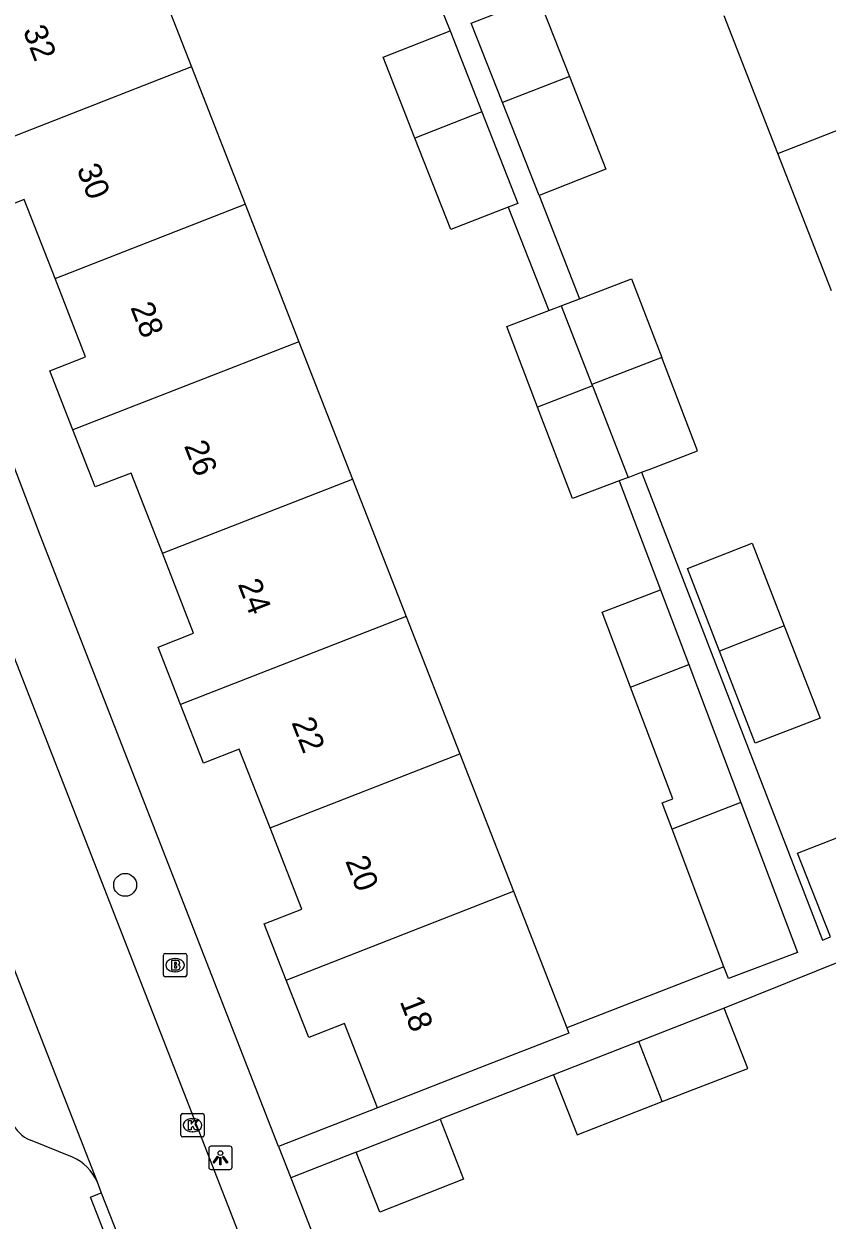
# Model space of a CAD drawing. Extents: x 159689 to 160786, y 387323 to 388339.
# Drawn here: x 160091.8 to 160126.1, y 387520.9 to 387572 of the extents above; entities that cross this region are included whole.
import ezdxf

# ---------------------------------------------------------------- set-up
doc = ezdxf.new("R2010")
doc.units = 0
for name, color, linetype in [('IMGEO_Boom', 7, 'Continuous'), ('IMGEO_Brandkraan', 7, 'Continuous'), ('IMGEO_Kolk', 7, 'Continuous'), ('IMGEO_Lichtpunt', 7, 'Continuous'), ('IMGEO_Pand', 7, 'Continuous'), ('IMGEO_Pand_nummerreeks', 7, 'Continuous'), ('IMGEO_Rijbaan_lokaal_open', 7, 'Continuous'), ('IMGEO_Voetpad_open', 7, 'Continuous')]:
    doc.layers.add(name, color=color, linetype=linetype)

msp = doc.modelspace()

# ---------------------------------------------------------------- linework, layer by layer
at = {"layer": 'IMGEO_Boom'}
msp.add_circle((160096.152, 387535.245), 0.489, dxfattribs=at)
at = {"layer": 'IMGEO_Brandkraan'}
for p, q in [((160097.786, 387531.391), (160097.786, 387532.243)), ((160097.861, 387532.317), (160098.713, 387532.317)), ((160098.787, 387532.243), (160098.787, 387531.391)), ((160098.274, 387532.097), (160098.299, 387532.097)), ((160098.713, 387531.317), (160097.861, 387531.317)), ((160098.297, 387531.537), (160098.272, 387531.537))]:
    msp.add_line(p, q, dxfattribs=at)
for points in [[(160097.786, 387531.391), (160097.786, 387532.243)], [(160097.861, 387532.317), (160098.713, 387532.317)], [(160098.787, 387532.243), (160098.787, 387531.391)], [(160098.134, 387532.017), (160098.134, 387531.617), (160098.347, 387531.617)], [(160098.365, 387532.017), (160098.134, 387532.017)], [(160098.313, 387531.936), (160098.259, 387531.936), (160098.259, 387531.86)], [(160098.259, 387531.86), (160098.312, 387531.86)], [(160098.321, 387531.784), (160098.259, 387531.784), (160098.259, 387531.703)], [(160098.259, 387531.703), (160098.321, 387531.703)], [(160098.713, 387531.317), (160097.861, 387531.317)]]:
    msp.add_lwpolyline(points, dxfattribs=at)
for centre, radius, start, end in [((160097.863, 387532.241), 0.0765, 91.552, 178.448), ((160097.863, 387532.241), 0.0765, 91.552, 178.448), ((160098.711, 387532.241), 0.0765, 1.552, 88.448), ((160098.711, 387532.241), 0.0765, 1.552, 88.448), ((160098.314, 387531.898), 0.0379, 267.8285, 90.9355), ((160098.322, 387531.743), 0.0404, 269.8759, 90.5077), ((160098.369, 387531.872), 0.145, 59.4692, 91.5367), ((160098.394, 387531.919), 0.0922, 285.5137, 58.1501), ((160098.399, 387531.727), 0.105, 301.3115, 78.989), ((160097.863, 387531.393), 0.0765, 181.552, 268.448), ((160097.863, 387531.393), 0.0765, 181.552, 268.448), ((160098.353, 387531.868), 0.251, 268.6676, 293.5347), ((160098.711, 387531.393), 0.0765, 271.552, 358.448), ((160098.711, 387531.393), 0.0765, 271.552, 358.448)]:
    msp.add_arc(centre, radius, start, end, dxfattribs=at)
for centre, major_axis, ratio, start_param, end_param in [((160098.273, 387531.817), (-0.387, 0.002), 0.722429, 4.712389, 7.853982), ((160098.298, 387531.817), (-0.39, 0.002), 0.717154, 1.570796, 4.712389)]:
    msp.add_ellipse(centre, major_axis=major_axis, ratio=ratio, start_param=start_param, end_param=end_param, dxfattribs=at)
at = {"layer": 'IMGEO_Kolk'}
for p, q in [((160098.531, 387524.551), (160098.531, 387525.403)), ((160098.606, 387525.477), (160099.458, 387525.477)), ((160099.019, 387525.257), (160099.044, 387525.257)), ((160099.532, 387525.403), (160099.532, 387524.551)), ((160099.042, 387524.697), (160099.017, 387524.697)), ((160099.458, 387524.477), (160098.606, 387524.477))]:
    msp.add_line(p, q, dxfattribs=at)
for points in [[(160098.531, 387524.551), (160098.531, 387525.403)], [(160098.606, 387525.477), (160099.458, 387525.477)], [(160098.852, 387525.177), (160098.975, 387525.177), (160098.975, 387525.026), (160099.105, 387525.177), (160099.269, 387525.177), (160099.123, 387525.026), (160099.276, 387524.777), (160099.124, 387524.777), (160099.039, 387524.941), (160098.975, 387524.874), (160098.975, 387524.777), (160098.852, 387524.777), (160098.852, 387525.177)], [(160099.532, 387525.403), (160099.532, 387524.551)], [(160099.458, 387524.477), (160098.606, 387524.477)]]:
    msp.add_lwpolyline(points, dxfattribs=at)
for centre, start, end in [((160098.608, 387525.401), 91.552, 178.448), ((160098.608, 387525.401), 91.552, 178.448), ((160099.456, 387525.401), 1.552, 88.448), ((160099.456, 387525.401), 1.552, 88.448), ((160098.608, 387524.553), 181.552, 268.448), ((160098.608, 387524.553), 181.552, 268.448), ((160099.456, 387524.553), 271.552, 358.448), ((160099.456, 387524.553), 271.552, 358.448)]:
    msp.add_arc(centre, 0.0765, start, end, dxfattribs=at)
for centre, major_axis, ratio, start_param, end_param in [((160099.018, 387524.977), (-0.387, 0.002), 0.722429, 4.712389, 7.853982), ((160099.043, 387524.977), (-0.39, 0.002), 0.717154, 1.570796, 4.712389)]:
    msp.add_ellipse(centre, major_axis=major_axis, ratio=ratio, start_param=start_param, end_param=end_param, dxfattribs=at)
at = {"layer": 'IMGEO_Lichtpunt'}
for p, q in [((160100.624, 387524.085), (160099.816, 387524.085)), ((160100.624, 387524.085), (160099.816, 387524.085)), ((160099.722, 387523.99), (160099.722, 387523.183)), ((160099.722, 387523.99), (160099.722, 387523.183)), ((160100.718, 387523.183), (160100.718, 387523.99)), ((160100.718, 387523.183), (160100.718, 387523.99)), ((160099.816, 387523.089), (160100.624, 387523.089)), ((160099.816, 387523.089), (160100.624, 387523.089))]:
    msp.add_line(p, q, dxfattribs=at)
for points in [[(160100.096, 387523.654), (160100.135, 387523.626), (160099.947, 387523.364), (160099.909, 387523.391), (160100.096, 387523.654)], [(160100.198, 387523.606), (160100.245, 387523.606), (160100.245, 387523.284), (160100.198, 387523.284), (160100.198, 387523.606)], [(160100.308, 387523.626), (160100.346, 387523.653), (160100.533, 387523.391), (160100.494, 387523.363), (160100.308, 387523.626)]]:
    msp.add_lwpolyline(points, dxfattribs=at)
msp.add_circle((160100.221, 387523.788), 0.0994, dxfattribs=at)
for centre, start, end in [((160099.816, 387523.99), 90, 180), ((160099.816, 387523.99), 90, 180), ((160100.624, 387523.99), 0, 90), ((160100.624, 387523.99), 0, 90), ((160099.816, 387523.183), 180, 270), ((160099.816, 387523.183), 180, 270), ((160100.624, 387523.183), 270, 0), ((160100.624, 387523.183), 270, 360)]:
    msp.add_arc(centre, 0.0946, start, end, dxfattribs=at)
at = {"layer": 'IMGEO_Pand'}
for points in [[(160096.697, 387576.052), (160098.989, 387570.183)], [(160110.938, 387572.052), (160113.797, 387573.175), (160115.13, 387569.781)], [(160124.032, 387566.492), (160121.745, 387572.362)], [(160108.53, 387567.146), (160107.174, 387570.597), (160110.033, 387571.719)], [(160110.033, 387571.719), (160111.39, 387568.263)], [(160112.268, 387568.665), (160110.938, 387572.052)], [(160098.989, 387570.183), (160089.379, 387566.43)], [(160098.989, 387570.183), (160101.281, 387564.315)], [(160124.032, 387566.492), (160133.59, 387570.221)], [(160115.13, 387569.781), (160112.268, 387568.665)], [(160115.13, 387569.781), (160116.689, 387565.81), (160113.831, 387564.687)], [(160113.831, 387564.687), (160112.268, 387568.665)], [(160111.39, 387568.263), (160108.53, 387567.146)], [(160111.39, 387568.263), (160112.926, 387564.355), (160112.513, 387564.193)], [(160112.513, 387564.193), (160110.067, 387563.232), (160108.53, 387567.146)], [(160126.319, 387560.621), (160124.032, 387566.492)], [(160093.159, 387561.143), (160091.842, 387564.514), (160090.354, 387563.933), (160089.379, 387566.43)], [(160093.159, 387561.143), (160101.281, 387564.315)], [(160101.281, 387564.315), (160103.574, 387558.447)], [(160093.923, 387554.679), (160092.937, 387557.201), (160094.465, 387557.798), (160093.159, 387561.143)], [(160115.554, 387560.279), (160117.787, 387561.134), (160119.074, 387557.774)], [(160114.247, 387559.779), (160114.775, 387559.981)], [(160114.775, 387559.981), (160115.554, 387560.279)], [(160114.775, 387559.981), (160116.089, 387556.612)], [(160113.771, 387555.648), (160112.453, 387559.091), (160114.247, 387559.779)], [(160103.574, 387558.447), (160093.923, 387554.679)], [(160103.574, 387558.447), (160105.866, 387552.579)], [(160119.074, 387557.774), (160116.089, 387556.612)], [(160118.212, 387552.87), (160118.531, 387552.992), (160120.601, 387553.785), (160119.074, 387557.774)], [(160116.109, 387556.561), (160113.771, 387555.648)], [(160116.089, 387556.612), (160116.109, 387556.561)], [(160116.109, 387556.561), (160117.635, 387552.649)], [(160117.255, 387552.503), (160115.267, 387551.742), (160113.771, 387555.648)], [(160097.745, 387549.407), (160096.405, 387552.837), (160094.876, 387552.24), (160093.923, 387554.679)], [(160117.635, 387552.649), (160117.255, 387552.503)], [(160117.635, 387552.649), (160118.212, 387552.87)], [(160097.745, 387549.407), (160105.866, 387552.579)], [(160105.866, 387552.579), (160108.158, 387546.711)], [(160121.541, 387545.23), (160120.17, 387548.765), (160122.939, 387549.839), (160124.308, 387546.31)], [(160098.517, 387542.946), (160097.556, 387545.405), (160099.076, 387545.999), (160097.745, 387549.407)], [(160117.739, 387543.688), (160116.527, 387546.899), (160119.027, 387547.843)], [(160119.027, 387547.843), (160120.229, 387544.661)], [(160108.158, 387546.711), (160098.517, 387542.946)], [(160108.158, 387546.711), (160110.45, 387540.842)], [(160124.308, 387546.31), (160125.837, 387542.369), (160123.068, 387541.295), (160121.541, 387545.23)], [(160124.308, 387546.31), (160121.541, 387545.23)], [(160117.739, 387543.688), (160120.229, 387544.661)], [(160120.229, 387544.661), (160122.453, 387538.766)], [(160119.512, 387537.618), (160119.086, 387538.746), (160119.54, 387538.917), (160117.739, 387543.688)], [(160102.34, 387537.675), (160101.024, 387541.045), (160099.493, 387540.448), (160098.517, 387542.946)], [(160102.34, 387537.675), (160110.45, 387540.842)], [(160110.45, 387540.842), (160112.742, 387534.974)], [(160122.453, 387538.766), (160119.512, 387537.618)], [(160122.453, 387538.766), (160124.872, 387532.358), (160121.918, 387531.243), (160121.726, 387531.751)], [(160103.032, 387531.182), (160102.094, 387533.584), (160103.694, 387534.209), (160102.34, 387537.675)], [(160121.726, 387531.751), (160119.512, 387537.618)], [(160126.275, 387533.021), (160124.879, 387536.597), (160127.654, 387537.681), (160128.416, 387535.73), (160130.197, 387536.425), (160130.785, 387534.923)], [(160103.032, 387531.182), (160112.742, 387534.974)], [(160112.742, 387534.974), (160115.024, 387529.133)], [(160106.936, 387525.72), (160105.527, 387529.326), (160103.992, 387528.726), (160103.032, 387531.182)], [(160121.746, 387529.978), (160118.097, 387528.553)], [(160119.098, 387525.986), (160122.75, 387527.408), (160121.746, 387529.978)], [(160115.024, 387529.133), (160115.11, 387528.913), (160111.594, 387527.54), (160106.936, 387525.72)], [(160118.097, 387528.553), (160114.455, 387527.131)], [(160119.098, 387525.986), (160118.097, 387528.553)], [(160114.455, 387527.131), (160115.454, 387524.566), (160119.098, 387525.986)], [(160109.602, 387525.235), (160110.609, 387522.679), (160107.035, 387521.27), (160106.027, 387523.827)], [(160106.027, 387523.827), (160109.602, 387525.235)]]:
    msp.add_lwpolyline(points, dxfattribs=at)
at = {"layer": 'IMGEO_Rijbaan_lokaal_open'}
for points in [[(160108.108, 387502.148), (160086.248, 387558.199), (160073.949, 387589.946)], [(160069.872, 387586.748), (160082.582, 387554.195), (160094.951, 387522.558)], [(160094.951, 387522.558), (160095.132, 387522.093)], [(160095.132, 387522.093), (160096.916, 387517.531), (160097.168, 387516.715)]]:
    msp.add_lwpolyline(points, dxfattribs=at)
at = {"layer": 'IMGEO_Voetpad_open'}
for points in [[(160102.702, 387524.071), (160092.528, 387550.187), (160079.92, 387583.288), (160078.337, 387587.445)], [(160108.237, 387576.163), (160110.033, 387571.719)], [(160113.831, 387564.687), (160115.554, 387560.279)], [(160112.513, 387564.193), (160114.247, 387559.779)], [(160118.212, 387552.87), (160125.946, 387532.883), (160126.275, 387533.021)], [(160117.255, 387552.503), (160119.027, 387547.843)], [(160149.389, 387541.094), (160121.746, 387529.978)], [(160121.726, 387531.751), (160115.024, 387529.133)], [(160114.455, 387527.131), (160109.602, 387525.235)], [(160106.936, 387525.72), (160102.702, 387524.071)], [(160093.909, 387523.61), (160092.105, 387524.337)], [(160102.702, 387524.071), (160103.223, 387522.735)], [(160106.027, 387523.827), (160103.223, 387522.735)], [(160103.223, 387522.735), (160111.039, 387502.671)], [(160097.168, 387516.715), (160096.761, 387516.556), (160094.667, 387521.911), (160095.132, 387522.093)]]:
    msp.add_lwpolyline(points, dxfattribs=at)
for centre, radius, start, end in [((160092.63, 387525.637), 1.402, 201.3871, 248.029), ((160093.118, 387521.784), 1.99, 22.8858, 66.567)]:
    msp.add_arc(centre, radius, start, end, dxfattribs=at)

# ---------------------------------------------------------------- texts
at = {"layer": 'IMGEO_Pand_nummerreeks'}
for s, rotation, p in [('32', 291.2154, (160091.773, 387571.744)), ('30', 291.2154, (160094.071, 387565.827)), ('28', 291.2154, (160096.366, 387559.915)), ('26', 291.2154, (160098.658, 387554.005)), ('24', 291.2154, (160100.953, 387548.093)), ('22', 291.2154, (160103.247, 387542.184)), ('20', 291.2154, (160105.545, 387536.267)), ('18', 291.2164, (160107.872, 387530.27))]:
    msp.add_text(s, height=1, rotation=rotation, dxfattribs=at).set_placement(p)

doc.saveas('drawing.dxf')
